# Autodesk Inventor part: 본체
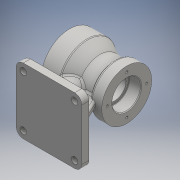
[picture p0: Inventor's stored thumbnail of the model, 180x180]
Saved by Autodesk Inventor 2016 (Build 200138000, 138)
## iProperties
Created: 2019-01
Part Number: 본체
Material: 일반
Document SubType Name: Modeling
Designer: USER
Density: 1 g/cm^3
Appearance: 기본값
Mass: 335.225 g
Surface Area: 600.378 cm^2
Volume: 335.225 cm^3
Author: USER
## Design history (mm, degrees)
sketch "스케치1"
  geometry: L1 (-40, 0)-(40, 0); L2 (-40, 0)-(-40, 40); L3 (-40, 40)-(-15, 40); L4 (2.321, 30)-(20.805, 30); L5 (20.805, 30)-(25, 35); L6 (25, 35)-(40, 35); L7 (40, 35)-(40, 0); L8 (-15, 40)-(2.321, 30); 2 further points
  constraints: 16 end point, 2 parallel, 2 perpendicular, 1 coincident, 1 horizontal, 1 midpoint, 1 vertical
  dimensions: "d0" = 80 distance of L1.start L1.end; "d1" = 80 diameter of L3 L1; "d2" = 70 diameter of L6 L1; "d3" = 60 diameter of L4 L1; "d4" = 25 distance of L2.end L3.end; "d5" = 15 distance of L6.end L5.end; "d7" = 30 deg angle of L8 L4; "d8" = 50 deg angle of L5 L4
revolve "회전1" sketch "스케치1" stored, may be unused: angle "d9" = 90 deg
node "작업 평면1"
sketch "스케치2"
  geometry: L1 (40, 40)-(40, -40) reference; L2 (35, 46)-(-57, 46); L3 (-57, 46)-(-57, -46); L4 (-57, -46)-(35, -46); L5 (35, -46)-(35, 46); L6 (35, 46)-(-57, -46); L7 (-57, 46)-(35, -46); 3 further points
  constraints: 12 end point, 3 midpoint, 2 parallel, 1 horizontal, 1 horizontal alignment, 1 perpendicular
  dimensions: "d88" = 5 distance between parallel lines of L5 L1; "d89" = 92 distance of L3.end L4.end; "d90" = 92 distance of L2.end L3.end
extrude "돌출1" join sketch "스케치2" distance "d13" = 10; taper "d14" = 0 deg
sketch "스케치5"
  geometry: C1 r 26 at (0, 0); 1 further point
  constraints: 1 centre point, 1 coincident
  dimensions: "d30" = 52 diameter of C1
extrude "돌출3" cut sketch "스케치5" distance "d31" = 20; taper "d32" = 0 deg
hole "구멍1" diameter "d35" = 32; stored, may be unused: countersink angle "d39" = 90 deg, drill point angle "d41" = 118 deg; dims "d33" = 10, "d34" = 10, "d36" = 6, "d37" = 40, "d38" = 17, "d40" = 76
chamfer "모따기1" distance "d42" = 1; stored, may be unused: second distance "d43" = 2, angle "d44" = 45 deg
sketch "스케치6"
  geometry: 2 further points
  dimensions: "d45" = 33 distance of point (0, 33) point (0, 0)
hole "구멍2" sketch "스케치6" at (0, 33) diameter "d46" = 3.242; stored, may be unused: countersink angle "d50" = 90 deg, drill point angle "d52" = 118 deg; dims "d47" = 9, "d48" = 40, "d49" = 17, "d51" = 11
sketch "스케치7"
  geometry: 2 further points
  constraints: 1 vertical alignment
  dimensions: "d56" = 27.5 distance of point (0, 27.5) point (0, 0)
hole "구멍3" sketch "스케치7" at (0, 27.5) diameter "d57" = 3.242; stored, may be unused: countersink angle "d61" = 90 deg, drill point angle "d63" = 118 deg; dims "d58" = 9, "d59" = 40, "d60" = 17, "d62" = 11
fillet "모깎기2" dims "d77" = 3
fillet "모깎기7" dims "d86" = 1
fillet "모깎기8" dims "d87" = 0.6
sketch "스케치9"
  geometry: L1 (-35, 46)-(-35, -46) reference; C1 r 16 at (-5, 0); 1 further point
  constraints: 1 centre point
  dimensions: "d91" = 30 distance from line of L1 C1.centre; "d92" = 32 diameter of C1
extrude "돌출4" join sketch "스케치9" stored distance "d93" = 20; taper "d94" = 0 deg
sketch "스케치10"
  geometry: L1 (57, -70)-(-35, -70) reference; L2 (47, -70)-(33.856, -41.813); L3 (57, -80)-(57, -70) reference; 1 further point
  constraints: 2 end point, 1 point on line
  dimensions: "d95" = 10 distance of L1.start L2.start; "d96" = 25 deg angle of L2 L3
feature "리브2" sketch "스케치10" dims "d97" = 1, "d98" = 10, "d99" = 0, "d100" = 0, "d101" = 1, "d102" = 1
fillet "모깎기9" dims "d103" = 10
fillet "모깎기10" dims "d104" = 3
fillet "모깎기11" dims "d105" = 3
fillet "모깎기12" dims "d106" = 3
hole "구멍5" diameter "d110" = 9; stored, may be unused: countersink angle "d114" = 90 deg, drill point angle "d116" = 118 deg; dims "d108" = 10, "d109" = 10, "d111" = 9, "d112" = 40, "d113" = 17, "d115" = 11
hole "구멍6" diameter "d119" = 9; stored, may be unused: countersink angle "d123" = 90 deg, drill point angle "d125" = 118 deg; dims "d117" = 10, "d118" = 10, "d120" = 9, "d121" = 40, "d122" = 17, "d124" = 11
node "솔리드1"
pattern_circular "원형 패턴1" dims angle "d54" = 360 deg
pattern_circular "원형 패턴2" dims angle "d65" = 360 deg
mirror "대칭3"
